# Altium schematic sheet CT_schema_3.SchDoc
size 218 x 258 mm
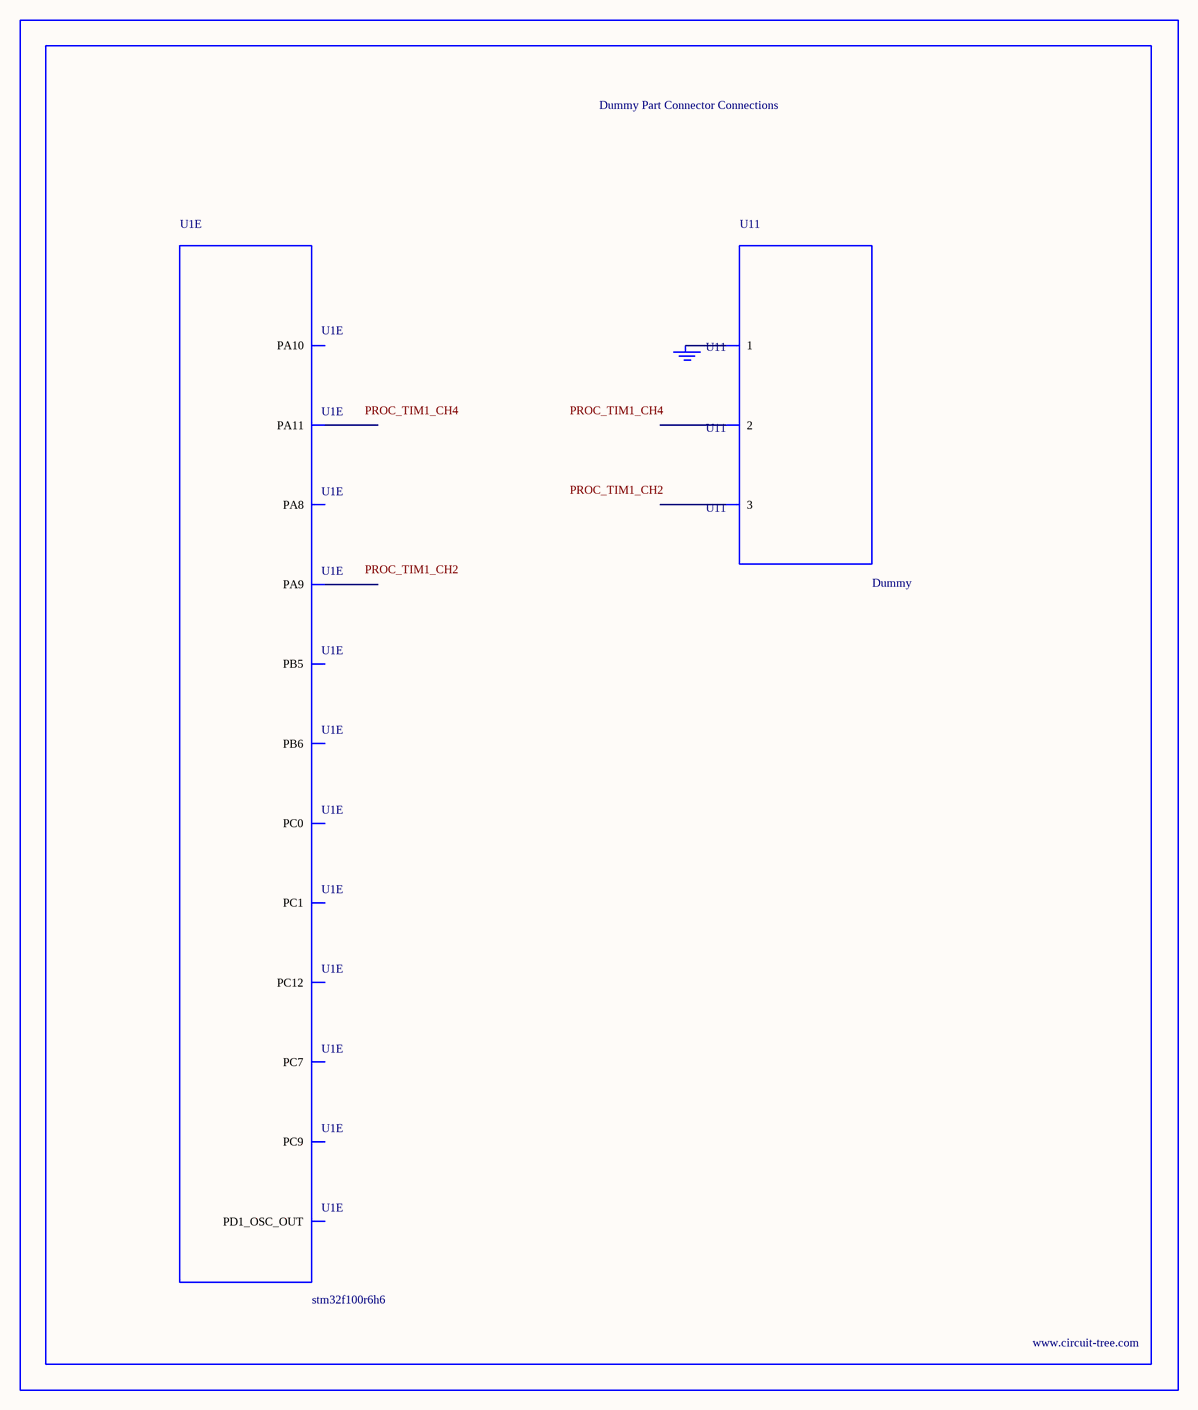
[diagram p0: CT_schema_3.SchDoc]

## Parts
BORDER2  (no value)
GND_INSTANCE_2_0  (no value)
U1  stm32f100r6h6  [TFBGA64]  (part E of 5)
U11  Dummy  [DUMMY_PACKAGE_110]

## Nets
NetGND_INSTANCE_2_0_0: GND_INSTANCE_2_0.0(GND) U11.1

Not connected (* = marked no-connect by the designer): U1 C4(PB5) C5(PC12) C6(PA10) C7(PA9) C8(PA11) D1(PD1_OSC_OUT) D3(PB6) D7(PA8) D8(PC9) E2(PC1) E3(PC0) E7(PC7); U11 2 3

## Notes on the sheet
- Labels drawn without touching a wire or pin: PROC_TIM1_CH2, PROC_TIM1_CH4

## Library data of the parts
BORDER2 = BORDER_PAGE2
GND_INSTANCE_2_0 = GND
